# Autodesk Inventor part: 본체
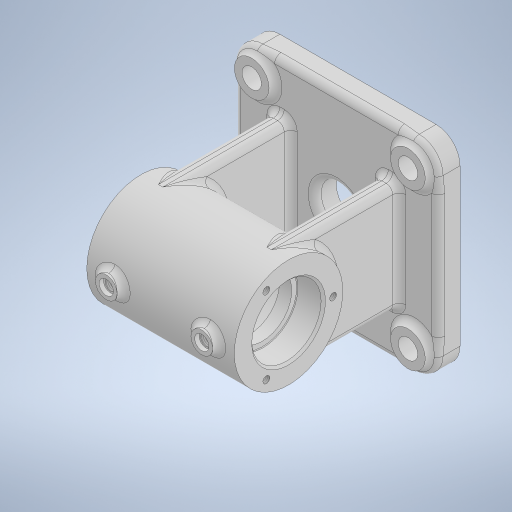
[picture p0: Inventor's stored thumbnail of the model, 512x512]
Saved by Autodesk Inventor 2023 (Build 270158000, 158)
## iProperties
Created: 2025-10
Part Number: 본체
Material: 일반
Document SubType Name: Modeling
Designer: home
Density: 1 g/cm^3
Appearance: 기본값
Mass: 186.774 g
Surface Area: 499.789 cm^2
Volume: 186.774 cm^3
Author: home
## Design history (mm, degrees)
sketch "스케치1"
  geometry: L1 (47, -47)-(-47, -47); L2 (-47, -47)-(-47, 47); L3 (-47, 47)-(47, 47); L4 (47, 47)-(47, -47); L5 (47, -47)-(-47, 47); L6 (-47, -47)-(47, 47); 1 further point
  constraints: 12 end point, 2 midpoint, 2 parallel, 1 horizontal, 1 perpendicular
  dimensions: "d0" = 94 distance of L2.end L3.end; "d1" = 94 distance of L3.end L1.start
extrude "돌출1" new body sketch "스케치1" distance "d2" = 10; taper "d3" = 0 deg
fillet "모깎기1" dims "d4" = 11
sketch "스케치2"
  geometry: C1 r 8 at (-36, 36); C2 r 8 at (36, 36); C3 r 8 at (36, -36); C4 r 8 at (-36, -36); A1 r 11 centre (-36, 36) between (-36, 47) and (-47, 36) reference; A2 r 11 centre (-36, -36) between (-47, -36) and (-36, -47) reference; A3 r 11 centre (36, -36) between (36, -47) and (47, -36) reference; A4 r 11 centre (36, 36) between (47, 36) and (36, 47) reference; 1 further point
  constraints: 4 centre point, 4 coincident
  dimensions: "d5" = 16 diameter of C1; "d6" = 16 diameter of C2; "d7" = 16 diameter of C3; "d8" = 16 diameter of C4
extrude "돌출2" join sketch "스케치2" distance "d9" = 3; taper "d10" = 0 deg
fillet "모깎기2" dims "d11" = 3
sketch "스케치3"
  geometry: C1 r 8 at (0, 0) reference; C2 r 8 at (-72, 0) reference; C3 r 8 at (-72, -72) reference; C4 r 8 at (0, -72) reference; 5 further points
  constraints: 4 coincident
hole "구멍1" sketch "스케치3" at (-72, 0), (0, 0), (0, -72), (-72, -72) diameter "d12" = 9; stored, may be unused: countersink angle "d16" = 90 deg, drill point angle "d18" = 118 deg; dims "d13" = 12, "d14" = 4, "d15" = 2, "d17" = 8
sketch "스케치4"
  geometry: L1 (72.174, 66)-(-70.978, 66); L2 (34, 66)-(34, 91); L3 (-36, 10)-(36, 10) reference; L4 (0, 10)-(0, 115.236); L5 (34, 91)-(0, 91); L6 (34, 82)-(22, 82); L7 (22, 82)-(22, 79.5); L8 (22, 79.5)-(16.258, 79.5); L9 (47, 0)-(36, 0) reference; L10 (16.258, 79.5)-(5, 86); L11 (5, 86)-(0, 86); L12 (-34, 82)-(-22, 82); L13 (-22, 82)-(-22, 79.5); L14 (-16.258, 79.5)-(-5, 86); L15 (-5, 86)-(0, 86); L16 (-34, 91)-(0, 91); L17 (-22, 79.5)-(-16.258, 79.5); L18 (-34, 82)-(-34, 91); 1 further point
  constraints: 32 end point, 6 symmetric about line, 5 perpendicular, 4 point on line, 3 vertical, 1 horizontal, 1 midpoint
  dimensions: "d19" = 12 distance from line of L2 L7.end; "d20" = 66 distance between parallel lines of L9 L1; "d22" = 34 distance between parallel lines of L2 L4; "d23" = 32 diameter of L6 L1; "d25" = 40 diameter of L11 L1; "d26" = 5 distance from line of L4 L10.end; "d27" = 27 diameter of L8 L1; "d28" = 30 deg angle of L8 L10; "d29" = 50 diameter of L5 L1
revolve "회전1" sketch "스케치4" stored, may be unused: angle "d30" = 90 deg
sketch "스케치5"
  geometry: L1 (47, -36)-(47, 36) reference; L2 (-47, 36)-(-47, -36) reference; L3 (-36, -47)-(36, -47) reference; L4 (36, 47)-(-36, 47) reference; L5 (-29, 25)-(-21, 25); L6 (-21, 25)-(-21, -25); L7 (-21, -25)-(-29, -25); L8 (-29, -25)-(-29, 25); 2 further points
  constraints: 8 end point, 2 parallel, 1 horizontal, 1 midpoint, 1 perpendicular
  dimensions: "d32" = 50 distance of L7.end L5.start; "d33" = 8 distance of L5.start L5.end; "d34" = 21 distance from line of point (0, 0) L6; "d35" = 0 vertical distance of point (-21, 0) point (0, 0)
extrude "돌출3" join sketch "스케치5" stored distance "d36" = 3; taper "d37" = 0 deg
fillet "모깎기3" dims "d38" = 3
fillet "모깎기4" dims "d39" = 3
fillet "모깎기5" dims "d40" = 3
node "작업 평면2"
sketch "스케치6"
  geometry: L1 (-34, 25)-(-34, -25) reference; C1 r 5 at (-22, 0); 1 further point
  constraints: 1 centre point
  dimensions: "d42" = 10 diameter of C1; "d43" = 12 distance from line of L1 C1.centre
extrude "돌출4" join sketch "스케치6" stored distance "d44" = 10; taper "d45" = 0 deg
sketch "스케치7"
  geometry: C1 r 5 at (0, 0) reference; C2 r 5 at (-44, 0) reference; 3 further points
  constraints: 2 coincident
hole "구멍2" sketch "스케치7" at (0, 0), (-44, 0) diameter "d46" = 5.1881; stored, may be unused: countersink angle "d50" = 90 deg, drill point angle "d52" = 118 deg; dims "d47" = 12, "d48" = 6.6, "d49" = 2, "d51" = 16
sketch "스케치8" dims "d53" = 41
  geometry: L1 (0, 0)-(-20.5, 0); C1 r 16 at (0, 0) reference; 2 further points
  constraints: 2 coincident, 2 end point, 1 horizontal, 1 horizontal alignment, 2 other
hole "구멍3" sketch "스케치8" at (-20.5, 0) diameter "d54" = 3.242; stored, may be unused: countersink angle "d58" = 90 deg, drill point angle "d60" = 118 deg; dims "d55" = 8, "d56" = 6.6, "d57" = 2, "d59" = 10
fillet "모깎기6" dims "d64" = 3
node "작업 평면4"
sketch "스케치9"
  geometry: C1 r 6 at (0, 0); 1 further point
  constraints: 1 centre point, 1 coincident
  dimensions: "d67" = 12 diameter of C1
extrude "돌출5" join sketch "스케치9" stored distance "d68" = 10; taper "d69" = 0 deg
sketch "스케치10"
  geometry: 2 further points
  constraints: 1 coincident
hole "구멍4" sketch "스케치10" at (0, 0) diameter "d70" = 5.1881; stored, may be unused: countersink angle "d74" = 90 deg, drill point angle "d76" = 0 deg; dims "d71" = 12, "d72" = 4, "d73" = 2, "d75" = 16
chamfer "모따기1" distance "d77" = 1; stored, may be unused: second distance "d78" = 2, angle "d79" = 45 deg
chamfer "모따기2" distance "d80" = 0.3; stored, may be unused: second distance "d81" = 2, angle "d82" = 45 deg
sketch "스케치11"
  geometry: 2 further points
  constraints: 1 coincident
hole "구멍5" sketch "스케치11" at (0, 0) diameter "d83" = 20; stored, may be unused: countersink angle "d87" = 90 deg, drill point angle "d89" = 0 deg; dims "d84" = 12, "d85" = 4, "d86" = 2, "d88" = 15
fillet "모깎기7" dims "d90" = 3
node "작업 평면5"
sketch "스케치12"
  geometry: L1 (-15.558, 3.5)-(15.558, 3.5); L2 (15.558, 3.5)-(15.558, -3.5); L3 (15.558, -3.5)-(-15.558, -3.5); L4 (-15.558, -3.5)-(-15.558, 3.5); L5 (-36, -66)-(36, -66) reference; 5 further points
  constraints: 3 midpoint, 2 other
  dimensions: "d91" = 0 vertical distance of point (26, 0) point (15.558, 0); "d92" = 0 horizontal distance of point (0, -66) point (0, 3.5)
feature "엠보싱1" sketch "스케치12" dims "d0" = 94, "d1" = 94, "d93" = 0.5, "d94" = 0
fillet "모깎기8" dims "d95" = 3
node "솔리드1"
mirror "미러1"
mirror "미러2"
pattern_circular "원형 패턴1" dims angle "d62" = 360 deg
mirror "미러3"
feature "A9D066F2-1C7D-4E18-AEED-F7BC21143FA4" dims "d12" = 9, "d13" = 12, "d14" = 4, "d15" = 2, "d16" = 90 deg, "d17" = 8, "d18" = 118 deg
other parameters: "d41" = -94, "d66" = -56
